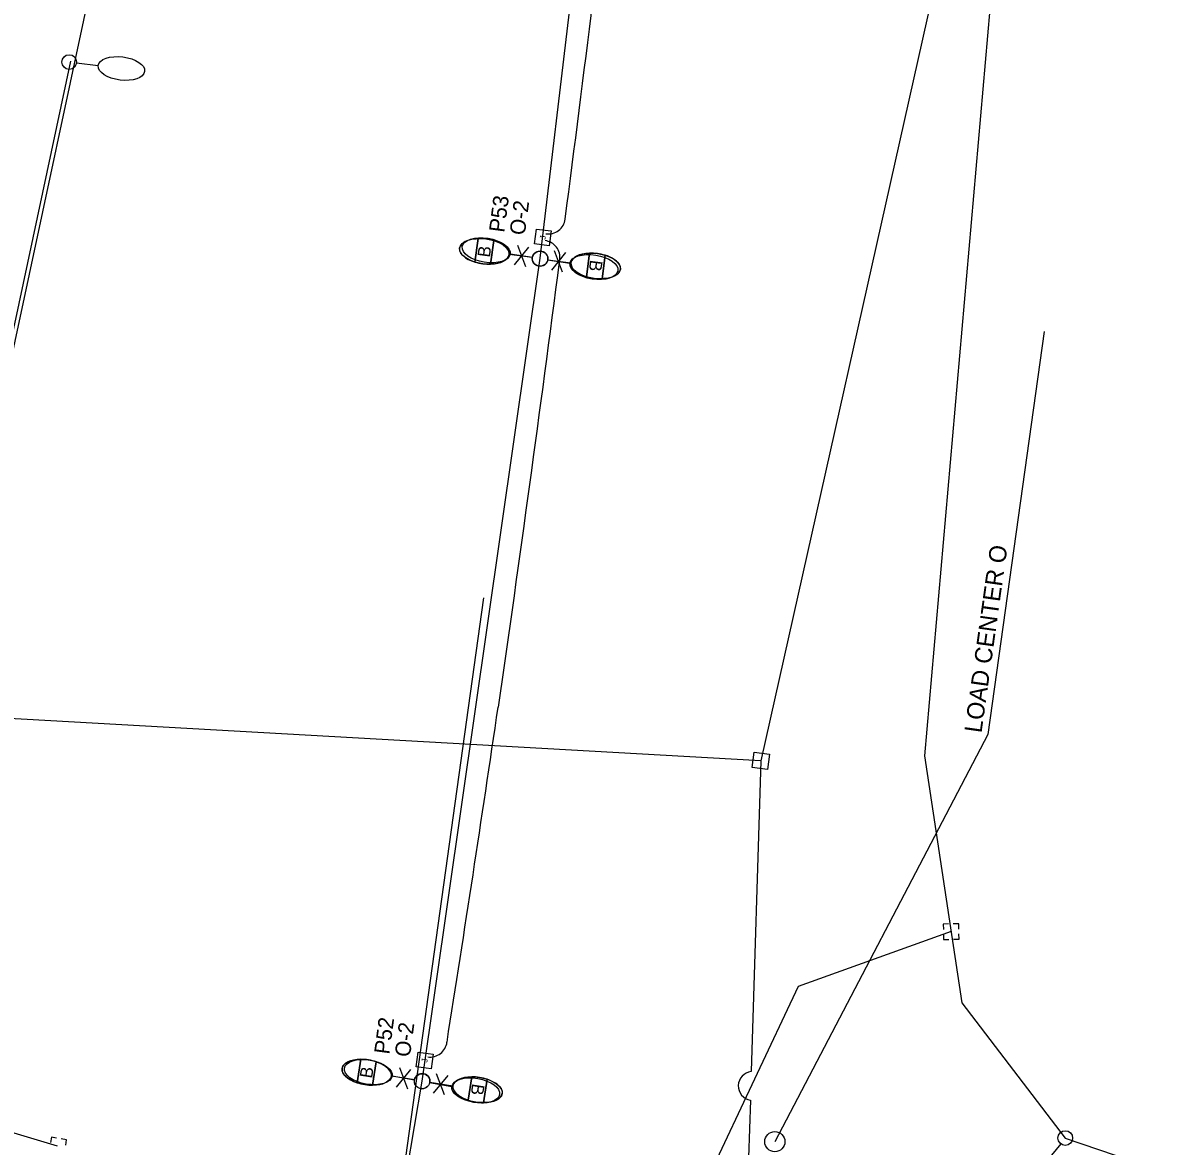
# Model space of a CAD drawing. Extents: x 925407 to 930994, y 604905 to 637063.
# Drawn here: x 930469.3 to 930840.2, y 618786.5 to 619149.9 of the extents above; entities that cross this region are included whole.
import ezdxf

# ---------------------------------------------------------------- set-up
doc = ezdxf.new("R2010")
doc.units = 0
for name, color, linetype in [('ActivePointCell_dp', 7, 'Continuous'), ('Conduit', 7, 'Continuous'), ('ConduitDB', 7, 'Continuous'), ('ConduitOT', 7, 'Continuous'), ('LiteCond_ep', 7, 'Continuous'), ('LoadCenter', 7, 'Continuous'), ('Miscellaneous2', 7, 'Continuous'), ('Miscellaneous9', 7, 'Continuous'), ('PoleLight', 7, 'Continuous'), ('PoleLight_ep', 7, 'Continuous'), ('PullBox', 7, 'Continuous')]:
    doc.layers.add(name, color=color, linetype=linetype)

msp = doc.modelspace()

# ---------------------------------------------------------------- linework, layer by layer
at = {"layer": 'ActivePointCell_dp'}
for p, q in [((930799.78, 619050.07), (930781.58, 618919.68)), ((930618.39, 618963.87), (930592.1, 618775.67))]:
    msp.add_line(p, q, dxfattribs=at)
msp.add_lwpolyline([(930781.58, 618919.68), (930712.64, 618787.89)], dxfattribs=at)
at = {"layer": 'Conduit'}
for p, q in [((930769.73, 618855.9), (930720.15, 618838.16)), ((930720.15, 618838.16), (930683.96, 618761.37)), ((930806.63, 618789.06), (930840.21, 618777.66))]:
    msp.add_line(p, q, dxfattribs=at)
msp.add_lwpolyline([(930783, 619163.1), (930761.07, 618912.81), (930773.1, 618832.87), (930806.63, 618789.06)], dxfattribs=at)
at = {"layer": 'ConduitDB'}
for p, q in [((930799.2, 619318.24), (930708.09, 618911.14)), ((930708.09, 618911.14), (930434.03, 618926.57))]:
    msp.add_line(p, q, dxfattribs=at)
at = {"layer": 'ConduitOT'}
for p, q in [((930708.09, 618911.14), (930705, 618810.59)), ((930704.72, 618801.33), (930704.15, 618782.79))]:
    msp.add_line(p, q, dxfattribs=at)
msp.add_lwpolyline([(930437.26, 618944.1), (930462.51, 619026.76), (930498.03, 619192.77)], dxfattribs=at)
for centre, radius, start, end in [((919241.37, 620573.8), 11500, 352.568878, 353.274926), ((930639.32, 619087.14), 5.5, 262.0326, 352.7998), ((930637.61, 619074.02), 5.5, 352.3329, 83.1001), ((919239.8, 620561.74), 11500, 351.835159, 352.560235), ((919246.94, 620611.54), 11500, 351.038186, 351.584511), ((930601.09, 618820.78), 5.5, 262.0326, 353.0658), ((930705.5, 618805.94), 4.68, 96.167, 260.3096)]:
    msp.add_arc(centre, radius, start, end, dxfattribs=at)
at = {"layer": 'LiteCond_ep'}
for p, q in [((930636.71, 619073.86), (930670.88, 619360.07)), ((930598.48, 618807.43), (930636.71, 619073.86)), ((930551.66, 618528.87), (930598.48, 618807.43))]:
    msp.add_line(p, q, dxfattribs=at)
msp.add_lwpolyline([(930480.53, 618786.47), (930405.6, 618808.83), (930420, 618890.96), (930437.37, 618952.26), (930461.74, 619029.85), (930484.82, 619137.52)], dxfattribs=at)
at = {"layer": 'LoadCenter'}
msp.add_circle((930712.64, 618787.89), 3.27, dxfattribs=at)
at = {"layer": 'Miscellaneous2'}
for p, q in [((930616.61, 619080.14), (930615.61, 619072.54)), ((930616.61, 619080.14), (930616.61, 619080.14)), ((930620.67, 619071.88), (930621.66, 619079.48)), ((930621.66, 619079.48), (930621.66, 619079.48)), ((930652.65, 619075.42), (930651.66, 619067.82)), ((930652.65, 619075.42), (930652.65, 619075.42)), ((930656.71, 619067.16), (930657.71, 619074.76)), ((930657.71, 619074.76), (930657.71, 619074.76)), ((930578.63, 618814.54), (930577.44, 618806.97)), ((930578.63, 618814.54), (930578.63, 618814.54)), ((930582.48, 618806.17), (930583.67, 618813.74)), ((930583.67, 618813.74), (930583.67, 618813.74)), ((930614.54, 618808.87), (930613.35, 618801.3)), ((930614.54, 618808.87), (930614.54, 618808.87)), ((930618.39, 618800.5), (930619.58, 618808.07)), ((930619.58, 618808.07), (930619.58, 618808.07))]:
    msp.add_line(p, q, dxfattribs=at)
for centre, major_axis, start_param, end_param in [((930618.64, 619076.01), (8.01, -1.05), 1.249648, 1.891946), ((930654.68, 619071.29), (8.01, -1.05), 1.249648, 1.891946), ((930618.64, 619076.01), (8.01, -1.05), 4.391241, 4.391271), ((930618.64, 619076.01), (8.01, -1.05), 4.391271, 5.033538), ((930654.68, 619071.29), (8.01, -1.05), 4.391241, 4.391271), ((930654.68, 619071.29), (8.01, -1.05), 4.391271, 5.033538), ((930580.56, 618810.36), (7.98, -1.26), 1.249648, 1.891946), ((930580.56, 618810.36), (7.98, -1.26), 4.391241, 4.391271), ((930580.56, 618810.36), (7.98, -1.26), 4.391271, 5.033538), ((930616.46, 618804.69), (7.98, -1.26), 1.249648, 1.891946), ((930616.46, 618804.69), (7.98, -1.26), 4.391241, 4.391271), ((930616.46, 618804.69), (7.98, -1.26), 4.391271, 5.033538)]:
    msp.add_ellipse(centre, major_axis=major_axis, ratio=0.5, start_param=start_param, end_param=end_param, dxfattribs=at)
at = {"layer": 'PoleLight'}
for p, q in [((930615.61, 619072.54), (930616.61, 619080.14)), ((930621.66, 619079.48), (930620.67, 619071.88)), ((930634.16, 619073.98), (930626.65, 619074.96)), ((930639.16, 619073.32), (930646.67, 619072.34)), ((930651.66, 619067.82), (930652.65, 619075.42)), ((930657.71, 619074.76), (930656.71, 619067.16)), ((930577.44, 618806.97), (930578.63, 618814.54)), ((930583.67, 618813.74), (930582.48, 618806.17)), ((930596.02, 618807.91), (930588.54, 618809.1)), ((930601, 618807.13), (930608.48, 618805.95)), ((930613.35, 618801.3), (930614.54, 618808.87)), ((930619.58, 618808.07), (930618.39, 618800.5))]:
    msp.add_line(p, q, dxfattribs=at)
for centre in [(930636.66, 619073.65), (930636.66, 619073.65), (930598.51, 618807.52), (930598.51, 618807.52)]:
    msp.add_circle(centre, 2.52, dxfattribs=at)
for centre, major_axis in [((930618.64, 619076.01), (8.01, -1.05)), ((930654.68, 619071.29), (8.01, -1.05)), ((930580.56, 618810.36), (7.98, -1.26)), ((930616.46, 618804.69), (7.98, -1.26))]:
    msp.add_ellipse(centre, major_axis=major_axis, ratio=0.5, dxfattribs=at)
for centre, major_axis, start_param, end_param in [((930618.64, 619076.01), (8.01, -1.05), 1.891945, 4.391241), ((930618.64, 619076.01), (8.01, -1.05), 0.847605, 1.249648), ((930618.64, 619076.01), (8.01, -1.05), 0, 0.847605), ((930618.64, 619076.01), (8.01, -1.05), 5.033538, 6.283185), ((930654.68, 619071.29), (8.01, -1.05), 1.891945, 4.391241), ((930654.68, 619071.29), (8.01, -1.05), 0.847605, 1.249648), ((930654.68, 619071.29), (8.01, -1.05), 0, 0.847605), ((930654.68, 619071.29), (8.01, -1.05), 5.033538, 6.283185), ((930580.56, 618810.36), (7.98, -1.26), 1.891945, 4.391241), ((930580.56, 618810.36), (7.98, -1.26), 0.847605, 1.249648), ((930580.56, 618810.36), (7.98, -1.26), 0, 0.847605), ((930580.56, 618810.36), (7.98, -1.26), 5.033538, 6.283185), ((930616.46, 618804.69), (7.98, -1.26), 1.891945, 4.391241), ((930616.46, 618804.69), (7.98, -1.26), 0.847605, 1.249648), ((930616.46, 618804.69), (7.98, -1.26), 0, 0.847605), ((930616.46, 618804.69), (7.98, -1.26), 5.033538, 6.283185)]:
    msp.add_ellipse(centre, major_axis=major_axis, ratio=0.5, start_param=start_param, end_param=end_param, dxfattribs=at)
at = {"layer": 'PoleLight_ep'}
for p, q in [((930486.64, 619137), (930493.69, 619136.13)), ((930628.37, 619071.68), (930632.98, 619077.4)), ((930629.35, 619077.97), (930632, 619071.11)), ((930634.24, 619074.03), (930626.97, 619075.16)), ((930639.08, 619073.28), (930646.34, 619072.15)), ((930644.95, 619075.62), (930640.34, 619069.9)), ((930643.97, 619069.33), (930641.32, 619076.19)), ((930590.16, 618805.58), (930594.85, 618811.24)), ((930591.23, 618811.85), (930593.78, 618804.96)), ((930596.06, 618807.84), (930588.81, 618809.08)), ((930600.89, 618807.02), (930608.14, 618805.78)), ((930606.79, 618809.28), (930602.1, 618803.63)), ((930605.72, 618803.01), (930603.17, 618809.9)), ((930805.14, 618787.21), (930800.68, 618781.69))]:
    msp.add_line(p, q, dxfattribs=at)
for centre, radius in [((930484.29, 619137.29), 2.37), ((930636.66, 619073.65), 2.45), ((930598.48, 618807.43), 2.45), ((930806.63, 618789.06), 2.37)]:
    msp.add_circle(centre, radius, dxfattribs=at)
for centre, major_axis in [((930501.2, 619135.19), (7.51, -0.93)), ((930619.23, 619076.36), (-7.75, 1.21)), ((930654.09, 619070.94), (7.75, -1.21)), ((930581.09, 618810.4), (-7.73, 1.32)), ((930615.86, 618804.47), (7.73, -1.32))]:
    msp.add_ellipse(centre, major_axis=major_axis, ratio=0.5, dxfattribs=at)
at = {"layer": 'PullBox'}
for p, q in [((930634.83, 619078.44), (930635.46, 619083.25)), ((930635.46, 619083.25), (930640.27, 619082.62)), ((930640.27, 619082.62), (930639.64, 619077.81)), ((930639.64, 619077.81), (930634.83, 619078.44)), ((930705.27, 618909.01), (930705.96, 618913.96)), ((930705.96, 618913.96), (930710.92, 618913.27)), ((930710.92, 618913.27), (930710.22, 618908.32)), ((930710.22, 618908.32), (930705.27, 618909.01)), ((930596.6, 618812.08), (930597.23, 618816.88)), ((930597.23, 618816.88), (930602.03, 618816.25)), ((930602.03, 618816.25), (930601.4, 618811.45)), ((930601.4, 618811.45), (930596.6, 618812.08))]:
    msp.add_line(p, q, dxfattribs=at)
for points in [[(930768.81, 618858.36), (930767.13, 618858.32), (930767.17, 618856.56)], [(930772.17, 618856.67), (930772.13, 618858.43), (930770.36, 618858.39)], [(930767.2, 618855.06), (930767.24, 618853.33), (930768.92, 618853.36)], [(930772.24, 618853.44), (930772.2, 618855.17)], [(930770.47, 618853.4), (930772.24, 618853.44)], [(930480.17, 618789.07), (930478.52, 618789.34), (930478.23, 618787.6)], [(930483.16, 618786.79), (930483.45, 618788.52), (930481.7, 618788.81)]]:
    msp.add_lwpolyline(points, dxfattribs=at)

# ---------------------------------------------------------------- texts
at = {"layer": 'ActivePointCell_dp'}
for s, height, rotation, p in [('P53', 5, 82.3882, (930625.06, 619081.94)), ('O-2', 5, 82.3882, (930631.7, 619081.06)), ('LOAD CENTER O', 5.6, 82.0566, (930779.5, 618919.97)), ('P52', 5, 82.3882, (930587.9, 618815.98)), ('O-2', 5, 82.3882, (930594.54, 618815.09))]:
    msp.add_text(s, height=height, rotation=rotation, dxfattribs=at).set_placement(p)
at = {"layer": 'Miscellaneous9'}
for rotation, p in [(82.5401, (930620.42, 619073.9)), (262.5401, (930652.9, 619073.4)), (81.029, (930582.28, 618808.2)), (261.029, (930614.74, 618806.85))]:
    msp.add_text('B', height=4.08, rotation=rotation, dxfattribs=at).set_placement(p)
at = {"layer": 'PullBox'}
for p in [(930638.43, 619079.75), (930600.19, 618813.39)]:
    msp.add_text('J', height=1.94, rotation=82.5422, dxfattribs=at).set_placement(p)

doc.saveas('drawing.dxf')
